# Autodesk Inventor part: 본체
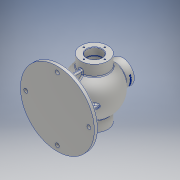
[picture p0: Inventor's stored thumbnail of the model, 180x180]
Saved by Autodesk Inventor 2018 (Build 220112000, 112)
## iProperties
Created: 2020-08
Part Number: 본체
Material: 알루미늄 6061
Document SubType Name: Modeling
Designer: home
Density: 2.7 g/cm^3
Appearance: 알루미늄 - 평지
Author: home
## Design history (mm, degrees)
sketch "스케치1"
  geometry: C1 r 85 at (0, 0); 1 further point
  constraints: 1 centre point, 1 coincident
  dimensions: "d0" = 170 diameter of C1
extrude "돌출1" new body sketch "스케치1" distance "d1" = 10; taper "d2" = 0 deg
sketch "스케치2"
  geometry: L1 (85, 150)-(85, -150); L2 (0, 85)-(0, -85) reference; L3 (116, -42.988)-(116, -68); L4 (116, -68)-(102.5, -68); L5 (102.5, -68)-(102.5, -39.278); L6 (116, 42.988)-(116, 68); L7 (116, 68)-(102.5, 68); L8 (102.5, 52)-(103.5, 52); L9 (103.5, 52)-(103.5, 50.25); L10 (103.5, 50.25)-(102.5, 50.25); L11 (102.5, 68)-(102.5, 52); L12 (102.5, 50.25)-(102.5, 39.278); A1 r 43 centre (85, 0) between (102.5, -39.278) and (102.5, 39.278); A2 r 53 centre (85, 0) between (116, -42.988) and (116, 42.988); 2 further points
  constraints: 22 end point, 8 perpendicular, 4 point on circle, 3 vertical, 2 centre point, 2 midpoint, 1 coincident, 1 horizontal, 1 horizontal alignment
  dimensions: "d3" = 85 distance between parallel lines of L2 L1; "d5" = 43 radius of A1; "d6" = 35 diameter of L5 L1; "d7" = 62 diameter of L3 L1; "d8" = 68 distance from line of L4 A2.centre; "d9" = 68 distance from line of A2.centre L7; "d10" = 62 diameter of L6 L1; "d12" = 53 radius of A2; "d13" = 150 vertical distance of point (0, 0) L1.start; "d14" = 150 distance of L1.end A2.centre; "d85" = 16 distance between parallel lines of L7 L8; "d86" = 1.75 distance between parallel lines of L10 L8; "d87" = 37 diameter of L9 L1; "d88" = 102.5 distance between parallel lines of L11 L2; "d89" = 102.5 distance between parallel lines of L12 L2
revolve "회전1" sketch "스케치2" stored, may be unused: angle "d15" = 90 deg
node "작업 평면1"
sketch "스케치3"
  geometry: C1 r 27 at (0, 0); 1 further point
  constraints: 1 centre point, 1 coincident
  dimensions: "d17" = 54 diameter of C1
extrude "돌출2" join sketch "스케치3" stored distance "d18" = 10; taper "d19" = 0 deg
sketch "스케치4"
  geometry: C1 r 13 at (0, 0); 1 further point
  constraints: 1 centre point, 1 coincident
  dimensions: "d20" = 26 diameter of C1
extrude "돌출3" cut sketch "스케치4" stored distance "d21" = 10; taper "d22" = 0 deg
sketch "스케치6"
  geometry: L1 (-1, 52)-(1, 52); L2 (4, 49)-(4, -49); L3 (1, -52)-(-1, -52); L4 (-4, -49)-(-4, 49); L5 (-40, 4)-(40, 4); L6 (43, 1)-(43, -1); L7 (40, -4)-(-40, -4); L8 (-43, -1)-(-43, 1); A1 r 3 centre (-40, -1) between (-43, -1) and (-40, -4); A2 r 3 centre (-40, 1) between (-40, 4) and (-43, 1); A3 r 3 centre (40, -1) between (40, -4) and (43, -1); A4 r 3 centre (40, 1) between (43, 1) and (40, 4); A5 r 3 centre (1, -49) between (1, -52) and (4, -49); A6 r 3 centre (-1, -49) between (-4, -49) and (-1, -52); A7 r 3 centre (-1, 49) between (-1, 52) and (-4, 49); A8 r 3 centre (1, 49) between (4, 49) and (1, 52); 1 further point
  constraints: 16 end point, 16 point on circle, 16 tangent, 8 centre point, 7 equal radius, 4 parallel, 2 horizontal, 2 perpendicular
  dimensions: "d29" = 4 distance from line of L5 point (0, 0); "d30" = 4 distance from line of L7 point (0, 0); "d31" = 4 distance from line of L2 point (0, 0); "d32" = 4 distance from line of point (0, 0) L4; "d33" = 104 distance between parallel lines of L1 L3; "d34" = 52 distance from line of L3 point (0, 0); "d35" = 86 distance between parallel lines of L6 L8; "d36" = 43 distance from line of point (0, 0) L8; "d37" = 3 radius of A1
extrude "돌출5" join sketch "스케치6" stored distance "d38" = 8; taper "d39" = 0 deg
sketch "스케치7"
  geometry: C1 r 17.5 at (0, 0) reference; 2 further points
  constraints: 1 vertical alignment
  dimensions: "d40" = 24 distance of C1.centre point (0, 24)
hole "구멍1" sketch "스케치7" at (0, 24) diameter "d41" = 3.242; stored, may be unused: countersink angle "d45" = 90 deg, drill point angle "d47" = 118 deg; dims "d42" = 12, "d43" = 4, "d44" = 2, "d46" = 15
sketch "스케치8"
  geometry: 2 further points
  constraints: 1 horizontal alignment
  dimensions: "d51" = 20 distance of point (-20, 0) point (0, 0)
hole "구멍2" sketch "스케치8" at (-20, 0) diameter "d52" = 3.242; stored, may be unused: countersink angle "d56" = 90 deg, drill point angle "d58" = 118 deg; dims "d53" = 12, "d54" = 4, "d55" = 2, "d57" = 15
chamfer "모따기1" distance "d64" = 1; stored, may be unused: second distance "d65" = 2, angle "d66" = 45 deg
fillet "모깎기1" dims "d67" = 3
sketch "스케치10"
  geometry: C1 r 4.5 at (0, -72.5); 1 further point
  constraints: 1 centre point, 1 vertical alignment
  dimensions: "d69" = 9 diameter of C1; "d70" = 72.5 distance of point (0, 0) C1.centre
extrude "돌출6" cut sketch "스케치10" extent not by distance; stored distance "d71" = 1.75; taper "d72" = 0 deg
node "작업 평면3"
node "작업 평면5"
sketch "스케치15"
  geometry: 2 further points
  constraints: 1 other
feature "엠보싱2" sketch "스케치15" dims "d83" = 0.5, "d84" = 0
node "솔리드1"
pattern_circular "원형 패턴1" dims angle "d49" = 360 deg
mirror "미러1"
pattern_circular "원형 패턴2" dims angle "d60" = 360 deg
pattern_circular "원형 패턴3" dims angle "d74" = 360 deg
other parameters: "d4" = 53, "d11" = 35, "d82" = -61
